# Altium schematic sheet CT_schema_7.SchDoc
size 293 x 258 mm
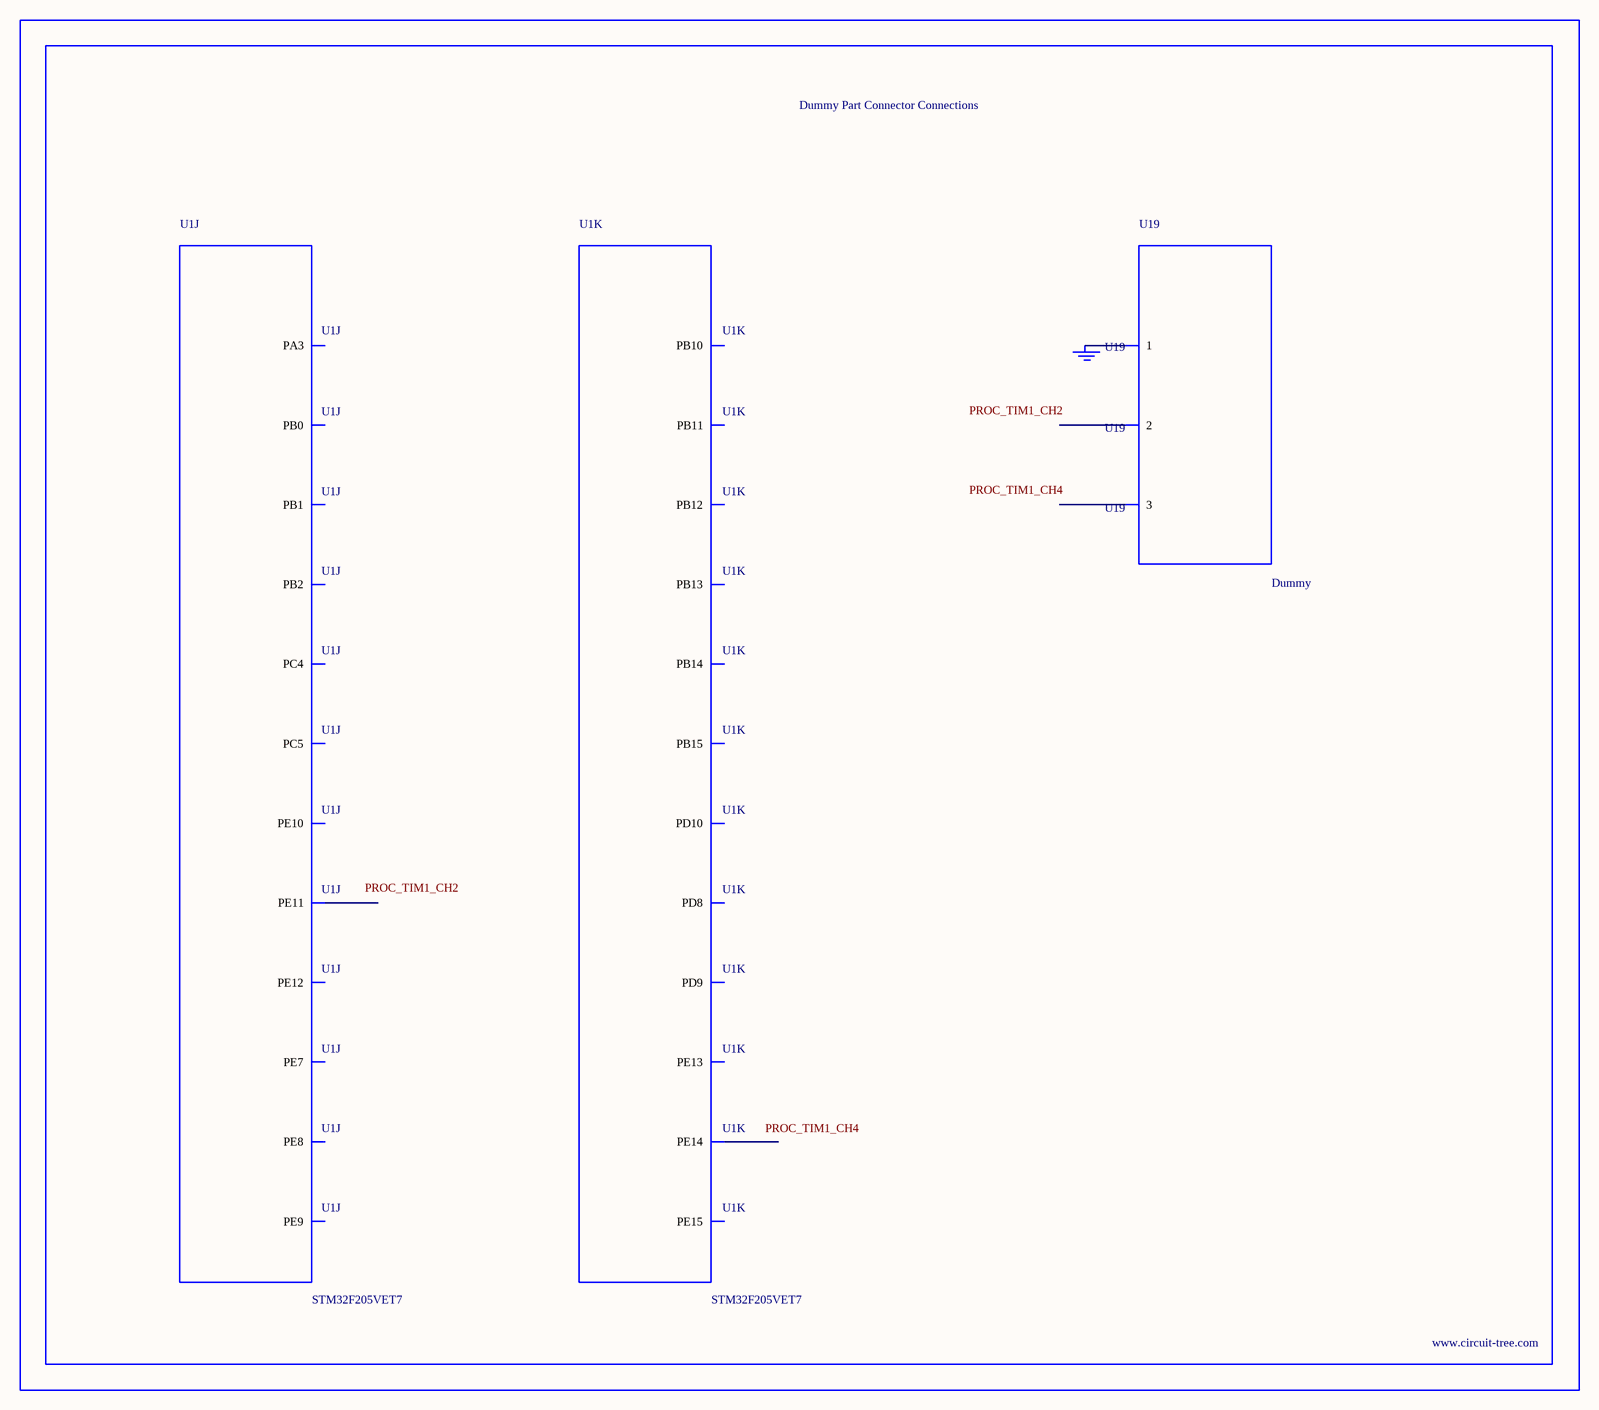
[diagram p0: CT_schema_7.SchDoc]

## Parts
BORDER6  (no value)
GND_INSTANCE_6_0  (no value)
U1  STM32F205VET7  [LQFP100]  (parts J,K of 11)
U19  Dummy  [DUMMY_PACKAGE_156]

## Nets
NetGND_INSTANCE_6_0_0: GND_INSTANCE_6_0.0(GND) U19.1

Not connected (* = marked no-connect by the designer): U1 26(PA3) 33(PC4) 34(PC5) 35(PB0) 36(PB1) 37(PB2) 38(PE7) 39(PE8) 40(PE9) 41(PE10) 42(PE11) 43(PE12) 44(PE13) 45(PE14) 46(PE15) 47(PB10) 48(PB11) 51(PB12) 52(PB13) 53(PB14) 54(PB15) 55(PD8) 56(PD9) 57(PD10); U19 2 3

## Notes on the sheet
- Labels drawn without touching a wire or pin: PROC_TIM1_CH2, PROC_TIM1_CH4

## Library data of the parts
BORDER6 = BORDER_PAGE6
GND_INSTANCE_6_0 = GND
